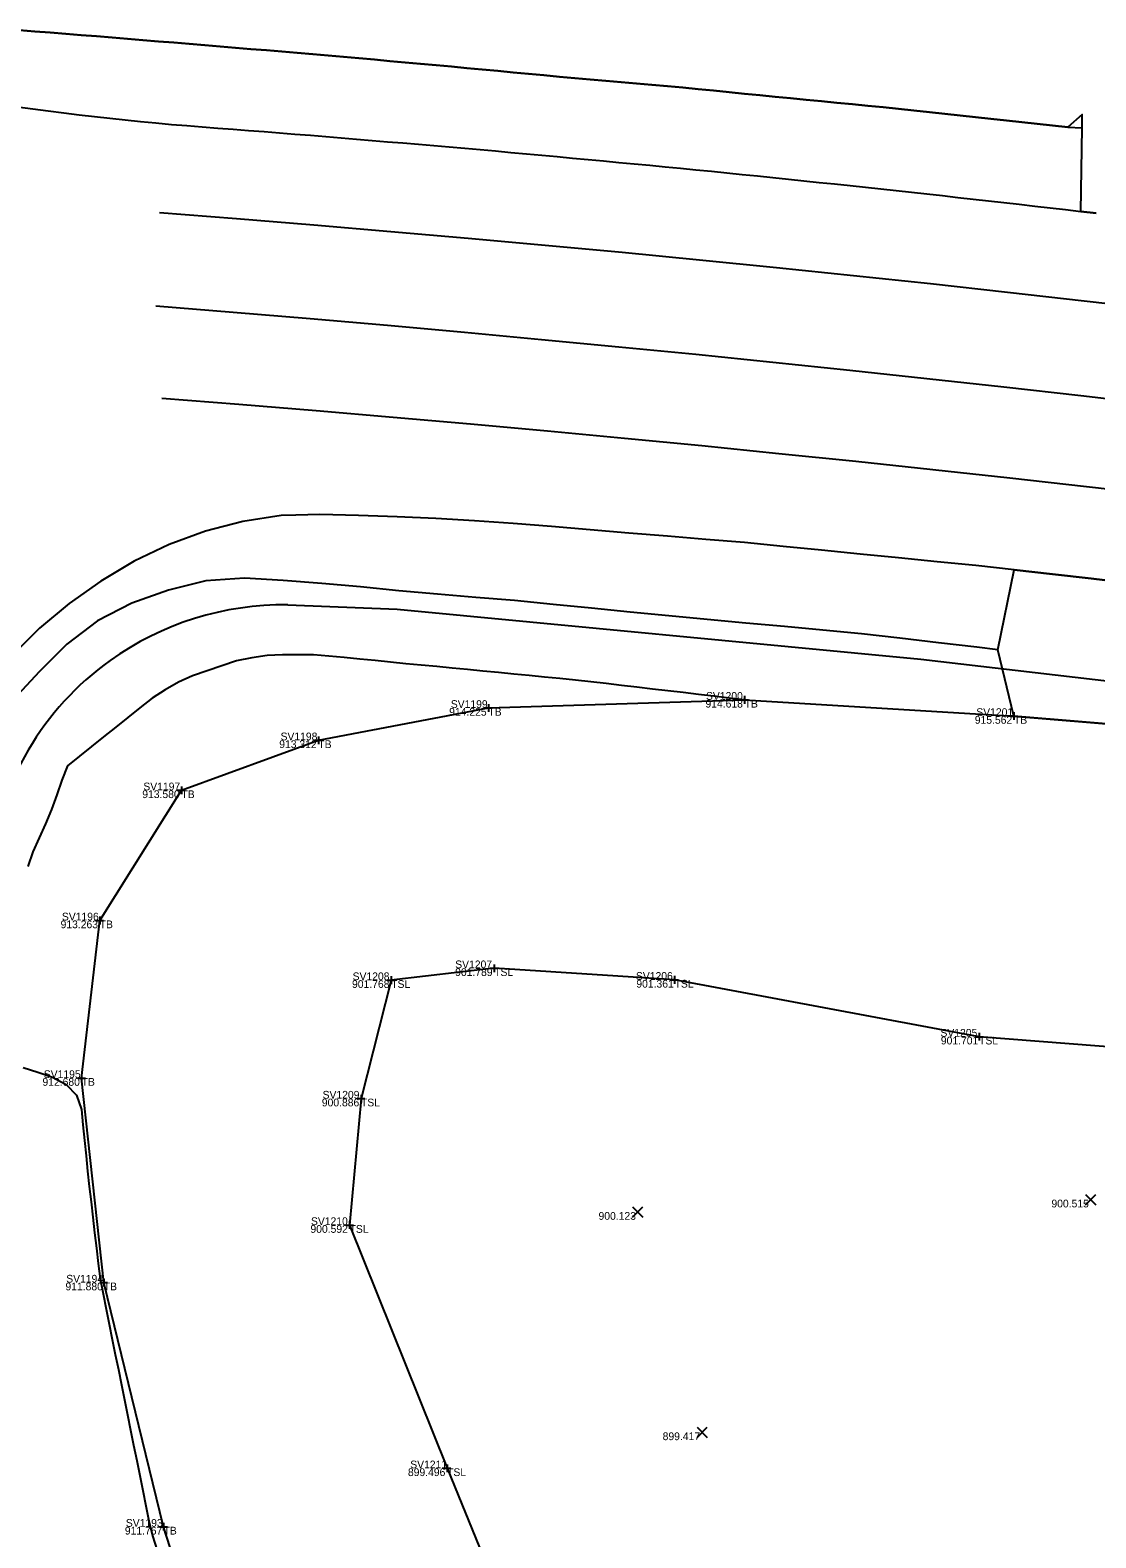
# Model space of a CAD drawing. Extents: x 1918148 to 1919797, y 624701 to 627089.
# Drawn here: x 1918938.4 to 1919076, y 625706.2 to 625900.9 of the extents above; entities that cross this region are included whole.
import ezdxf

# ---------------------------------------------------------------- set-up
doc = ezdxf.new("R2010")
doc.units = 0
for name, color, linetype in [('DT_X_Terrain_Boundary', 7, 'Continuous'), ('PM_X_Channelizing_Line', 7, 'Continuous'), ('PM_X_CL_Double_Solid', 7, 'Continuous'), ('PM_X_Edge_Line', 7, 'Continuous'), ('PM_X_Lane_Line', 7, 'Continuous'), ('PV_X_Shoulder_Aggregate', 7, 'Continuous'), ('RD_X_Concrete_Pad', 7, 'Continuous'), ('RD_X_GR_Rt', 7, 'Continuous'), ('SV_X_Random_Point', 7, 'Continuous'), ('SV_X_Shot_Marker', 7, 'Continuous'), ('SV_X_Text_Comment', 7, 'Continuous'), ('SV_X_Text_Elevation', 7, 'Continuous'), ('SV_X_Text_Name', 7, 'Continuous'), ('SV_X_Toe_of_Slope', 7, 'Continuous'), ('SV_X_Top_of_Bank', 7, 'Continuous')]:
    doc.layers.add(name, color=color, linetype=linetype)

msp = doc.modelspace()

# ---------------------------------------------------------------- linework, layer by layer
at = {"layer": 'DT_X_Terrain_Boundary'}
for points in [[(1919076.08, 625877.29), (1919074.09, 625877.53), (1919074.28, 625888.32), (1919074.28, 625890.06), (1919072.42, 625888.4), (1919070.43, 625888.62), (1919068.44, 625888.84), (1919066.45, 625889.05), (1919064.47, 625889.27), (1919062.48, 625889.49), (1919060.49, 625889.71), (1919058.5, 625889.92), (1919056.51, 625890.14), (1919054.53, 625890.36), (1919052.54, 625890.57), (1919050.55, 625890.77), (1919048.56, 625890.97), (1919046.57, 625891.16), (1919044.58, 625891.36), (1919042.59, 625891.55), (1919040.6, 625891.75), (1919038.6, 625891.95), (1919036.61, 625892.14), (1919034.62, 625892.34), (1919032.63, 625892.54), (1919030.64, 625892.73), (1919028.65, 625892.93), (1919026.66, 625893.12), (1919024.67, 625893.32), (1919022.68, 625893.52), (1919020.69, 625893.7), (1919018.7, 625893.88), (1919016.71, 625894.05), (1919014.71, 625894.23), (1919012.72, 625894.4), (1919010.73, 625894.56), (1919008.73, 625894.73), (1919006.74, 625894.91), (1919004.75, 625895.1), (1919002.76, 625895.29), (1919000.77, 625895.48), (1918998.78, 625895.66), (1918996.79, 625895.85), (1918994.8, 625896.04), (1918992.8, 625896.22), (1918990.81, 625896.4), (1918988.82, 625896.59), (1918986.83, 625896.77), (1918984.84, 625896.95), (1918982.85, 625897.13), (1918980.85, 625897.31), (1918978.86, 625897.49), (1918976.87, 625897.66), (1918974.88, 625897.83), (1918972.88, 625898), (1918970.89, 625898.17), (1918968.9, 625898.34), (1918966.9, 625898.5), (1918964.91, 625898.67), (1918962.92, 625898.83), (1918960.93, 625899), (1918958.93, 625899.16), (1918956.94, 625899.33), (1918954.95, 625899.49), (1918952.95, 625899.65), (1918950.96, 625899.82), (1918948.97, 625899.98), (1918946.97, 625900.14), (1918944.98, 625900.3), (1918942.98, 625900.46), (1918940.99, 625900.62), (1918939, 625900.78), (1918937, 625900.93)], [(1919200.65, 625791.17), (1919111.29, 625808.54), (1919090.36, 625810.28), (1919065.45, 625812.35), (1919063.39, 625820.89), (1919065.48, 625831.23), (1919070.44, 625830.66), (1919075.41, 625830.09), (1919080.38, 625829.52), (1919085.35, 625828.96), (1919090.31, 625828.39), (1919095.28, 625827.8), (1919100.24, 625827.2), (1919105.21, 625826.6), (1919110.17, 625826), (1919115.14, 625825.41), (1919120.1, 625824.81), (1919124.48, 625836), (1919134.4, 625834.72), (1919144.31, 625833.4), (1919154.22, 625832.06)]]:
    msp.add_lwpolyline(points, dxfattribs=at)
at = {"layer": 'PM_X_Channelizing_Line'}
msp.add_lwpolyline([(1918955.09, 625877.37), (1918965.06, 625876.6), (1918975.03, 625875.79), (1918984.99, 625874.95), (1918994.95, 625874.08), (1919004.91, 625873.18), (1919014.87, 625872.24), (1919024.82, 625871.28), (1919034.77, 625870.28), (1919044.72, 625869.26), (1919054.67, 625868.2), (1919064.61, 625867.11), (1919074.54, 625865.99), (1919084.48, 625864.84), (1919094.41, 625863.66), (1919104.33, 625862.45), (1919114.25, 625861.2), (1919124.17, 625859.93), (1919134.09, 625858.62), (1919144, 625857.29), (1919153.9, 625855.92), (1919160.39, 625855.01)], dxfattribs=at)
at = {"layer": 'PM_X_CL_Double_Solid'}
msp.add_lwpolyline([(1918954.64, 625865.34), (1918964.6, 625864.53), (1918974.57, 625863.69), (1918984.53, 625862.82), (1918994.49, 625861.93), (1919004.45, 625861), (1919014.4, 625860.05), (1919024.35, 625859.07), (1919034.3, 625858.06), (1919044.25, 625857.03), (1919054.19, 625855.96), (1919064.13, 625854.87), (1919074.07, 625853.75), (1919084, 625852.6), (1919093.93, 625851.42), (1919103.86, 625850.22), (1919113.79, 625848.98), (1919123.71, 625847.72), (1919133.62, 625846.43), (1919143.53, 625845.11), (1919153.44, 625843.77), (1919160.7, 625842.77)], dxfattribs=at)
at = {"layer": 'PM_X_Edge_Line'}
for points in [[(1918936.77, 625891.05), (1918938.75, 625890.76), (1918940.73, 625890.5), (1918942.72, 625890.25), (1918944.7, 625890.01), (1918946.69, 625889.77), (1918948.67, 625889.55), (1918950.66, 625889.34), (1918952.65, 625889.14), (1918954.64, 625888.95), (1918956.64, 625888.77), (1918958.63, 625888.6), (1918960.62, 625888.44), (1918962.62, 625888.29), (1918964.61, 625888.14), (1918966.61, 625887.98), (1918968.6, 625887.83), (1918970.59, 625887.67), (1918972.59, 625887.51), (1918974.58, 625887.35), (1918976.57, 625887.19), (1918978.57, 625887.03), (1918980.56, 625886.87), (1918982.55, 625886.7), (1918984.55, 625886.53), (1918986.54, 625886.37), (1918988.53, 625886.2), (1918990.53, 625886.03), (1918992.52, 625885.85), (1918994.51, 625885.68), (1918996.5, 625885.5), (1918998.49, 625885.33), (1919000.49, 625885.15), (1919002.48, 625884.97), (1919004.47, 625884.79), (1919006.46, 625884.6), (1919008.45, 625884.42), (1919010.44, 625884.23), (1919012.44, 625884.05), (1919014.43, 625883.86), (1919016.42, 625883.67), (1919018.41, 625883.48), (1919020.4, 625883.28), (1919022.39, 625883.09), (1919024.38, 625882.89), (1919026.37, 625882.7), (1919028.36, 625882.5), (1919030.35, 625882.3), (1919032.34, 625882.1), (1919034.33, 625881.89), (1919036.32, 625881.69), (1919038.31, 625881.48), (1919040.3, 625881.27), (1919042.29, 625881.07), (1919044.28, 625880.86), (1919046.26, 625880.64), (1919048.25, 625880.43), (1919050.24, 625880.22), (1919052.23, 625880), (1919054.22, 625879.78), (1919056.21, 625879.56), (1919058.19, 625879.34), (1919060.18, 625879.12), (1919062.17, 625878.9), (1919064.16, 625878.67), (1919066.14, 625878.45), (1919068.13, 625878.22), (1919070.12, 625877.99), (1919072.1, 625877.76), (1919074.09, 625877.53), (1919076.08, 625877.29)], [(1918972.72, 625838.3), (1918970.79, 625838.25), (1918965.86, 625837.46), (1918961.02, 625836.21), (1918956.33, 625834.49), (1918951.81, 625832.35), (1918947.52, 625829.78), (1918943.44, 625826.9), (1918939.6, 625823.69), (1918936.06, 625820.17)], [(1919080.38, 625829.52), (1919075.41, 625830.09), (1919070.44, 625830.66), (1919065.48, 625831.23), (1919060.51, 625831.78), (1919055.53, 625832.27), (1919050.56, 625832.77), (1919045.58, 625833.27), (1919040.61, 625833.76), (1919035.63, 625834.26), (1919030.65, 625834.74), (1919025.67, 625835.15), (1919020.69, 625835.57), (1919015.7, 625835.98), (1919010.72, 625836.4), (1919005.74, 625836.81), (1919000.76, 625837.22), (1918995.77, 625837.56), (1918990.78, 625837.85), (1918985.78, 625838.08), (1918980.78, 625838.26), (1918975.79, 625838.38), (1918972.72, 625838.3)]]:
    msp.add_lwpolyline(points, dxfattribs=at)
at = {"layer": 'PM_X_Lane_Line'}
msp.add_lwpolyline([(1918955.39, 625853.42), (1918965.36, 625852.63), (1918975.33, 625851.81), (1918985.29, 625850.96), (1918995.25, 625850.08), (1919005.21, 625849.17), (1919015.17, 625848.23), (1919025.12, 625847.27), (1919035.07, 625846.27), (1919045.02, 625845.25), (1919054.96, 625844.19), (1919064.9, 625843.11), (1919074.84, 625842), (1919084.78, 625840.86), (1919094.71, 625839.69), (1919104.63, 625838.49), (1919114.56, 625837.26), (1919124.48, 625836), (1919134.4, 625834.72), (1919144.31, 625833.4), (1919154.22, 625832.06), (1919164.12, 625830.68), (1919174.03, 625829.28), (1919193.35, 625826.46)], dxfattribs=at)
at = {"layer": 'PV_X_Shoulder_Aggregate'}
for points in [[(1919030.67, 625814.44), (1919028.68, 625814.67), (1919026.69, 625814.91), (1919024.71, 625815.14), (1919022.72, 625815.37), (1919020.73, 625815.6), (1919018.75, 625815.83), (1919016.76, 625816.06), (1919014.77, 625816.3), (1919012.79, 625816.53), (1919010.8, 625816.76), (1919008.82, 625816.99), (1919006.82, 625817.19), (1919004.83, 625817.38), (1919002.84, 625817.57), (1919000.85, 625817.76), (1918998.86, 625817.96), (1918996.87, 625818.15), (1918994.88, 625818.34), (1918992.89, 625818.54), (1918990.9, 625818.73), (1918988.91, 625818.92), (1918986.92, 625819.11), (1918984.93, 625819.31), (1918982.94, 625819.5), (1918980.95, 625819.69), (1918978.96, 625819.89), (1918976.96, 625820.08), (1918974.97, 625820.24), (1918972.98, 625820.26), (1918970.98, 625820.27), (1918968.98, 625820.16), (1918967, 625819.86), (1918965.05, 625819.49), (1918963.16, 625818.83), (1918961.27, 625818.18), (1918959.37, 625817.53), (1918957.56, 625816.71), (1918955.81, 625815.75), (1918954.13, 625814.67), (1918952.57, 625813.42), (1918951.01, 625812.17), (1918949.45, 625810.92), (1918947.88, 625809.67), (1918946.32, 625808.42), (1918944.76, 625807.17), (1918943.2, 625805.92), (1918942.5, 625804.05), (1918941.83, 625802.17), (1918941.16, 625800.28), (1918940.38, 625798.44), (1918939.56, 625796.62), (1918938.74, 625794.79), (1918938.08, 625792.91)], [(1918937.48, 625766.95), (1918939.38, 625766.34), (1918941.26, 625765.69), (1918943.03, 625764.75), (1918944.38, 625763.36), (1918945.02, 625761.52), (1918945.21, 625759.53), (1918945.41, 625757.54), (1918945.61, 625755.55), (1918945.81, 625753.56), (1918946.01, 625751.57), (1918946.25, 625749.59), (1918946.48, 625747.6), (1918946.71, 625745.61), (1918946.95, 625743.63), (1918947.18, 625741.64), (1918947.42, 625739.66), (1918947.82, 625737.7), (1918948.21, 625735.75), (1918948.6, 625733.8), (1918949, 625731.84), (1918949.39, 625729.89), (1918949.79, 625727.94), (1918950.18, 625725.98), (1918950.57, 625724.03), (1918950.97, 625722.08), (1918951.36, 625720.12), (1918951.75, 625718.17), (1918952.15, 625716.21), (1918952.54, 625714.26), (1918952.93, 625712.31), (1918953.33, 625710.35), (1918953.72, 625708.4), (1918954.19, 625706.47), (1918954.81, 625704.56)]]:
    msp.add_lwpolyline(points, dxfattribs=at)
at = {"layer": 'RD_X_Concrete_Pad'}
for points in [[(1918937, 625900.93), (1918939, 625900.78), (1918940.99, 625900.62), (1918942.98, 625900.46), (1918944.98, 625900.3), (1918946.97, 625900.14), (1918948.97, 625899.98), (1918950.96, 625899.82), (1918952.95, 625899.65), (1918954.95, 625899.49), (1918956.94, 625899.33), (1918958.93, 625899.16), (1918960.93, 625899), (1918962.92, 625898.83), (1918964.91, 625898.67), (1918966.9, 625898.5), (1918968.9, 625898.34), (1918970.89, 625898.17), (1918972.88, 625898), (1918974.88, 625897.83), (1918976.87, 625897.66), (1918978.86, 625897.49), (1918980.85, 625897.31), (1918982.85, 625897.13), (1918984.84, 625896.95), (1918986.83, 625896.77), (1918988.82, 625896.59), (1918990.81, 625896.4), (1918992.8, 625896.22), (1918994.8, 625896.04), (1918996.79, 625895.85), (1918998.78, 625895.66), (1919000.77, 625895.48), (1919002.76, 625895.29), (1919004.75, 625895.1), (1919006.74, 625894.91), (1919008.73, 625894.73), (1919010.73, 625894.56), (1919012.72, 625894.4), (1919014.71, 625894.23), (1919016.71, 625894.05), (1919018.7, 625893.88), (1919020.69, 625893.7), (1919022.68, 625893.52), (1919024.67, 625893.32), (1919026.66, 625893.12), (1919028.65, 625892.93), (1919030.64, 625892.73), (1919032.63, 625892.54), (1919034.62, 625892.34), (1919036.61, 625892.14), (1919038.6, 625891.95), (1919040.6, 625891.75), (1919042.59, 625891.55), (1919044.58, 625891.36), (1919046.57, 625891.16), (1919048.56, 625890.97), (1919050.55, 625890.77), (1919052.54, 625890.57), (1919054.53, 625890.36), (1919056.51, 625890.14), (1919058.5, 625889.92), (1919060.49, 625889.71), (1919062.48, 625889.49), (1919064.47, 625889.27), (1919066.45, 625889.05), (1919068.44, 625888.84), (1919070.43, 625888.62), (1919072.42, 625888.4), (1919074.28, 625888.32), (1919074.28, 625890.06)], [(1919063.39, 625820.89), (1919060.65, 625821.25), (1919055.69, 625821.82), (1919050.72, 625822.39), (1919045.75, 625822.95), (1919040.77, 625823.42), (1919035.8, 625823.89), (1919030.82, 625824.36), (1919025.84, 625824.83), (1919020.86, 625825.3), (1919015.88, 625825.77), (1919010.91, 625826.27), (1919005.93, 625826.76), (1919000.96, 625827.25), (1918995.97, 625827.67), (1918990.99, 625828.09), (1918986.01, 625828.53), (1918981.04, 625829.03), (1918976.06, 625829.47), (1918971.07, 625829.85), (1918966.08, 625830.16), (1918961.1, 625829.79), (1918956.25, 625828.6), (1918951.54, 625826.92), (1918947.09, 625824.66), (1918943.11, 625821.64), (1918939.58, 625818.11), (1918936.21, 625814.42)]]:
    msp.add_lwpolyline(points, dxfattribs=at)
at = {"layer": 'RD_X_GR_Rt'}
msp.add_lwpolyline([(1918971.66, 625826.7), (1918985.81, 625826.14), (1919053.44, 625819.71), (1919110.63, 625813)], dxfattribs=at)
for centre, radius, start, end in [((1918971.1, 625788.29), 38.41, 89.1608, 125.641), ((1918970.05, 625789.38), 36.91, 125.2973, 174.3384)]:
    msp.add_arc(centre, radius, start, end, dxfattribs=at)
at = {"layer": 'SV_X_Random_Point'}
for p, q in [((1919074.69, 625749.22), (1919076.02, 625750.55)), ((1919074.69, 625750.55), (1919076.02, 625749.22)), ((1919016.18, 625747.62), (1919017.51, 625748.95)), ((1919016.18, 625748.95), (1919017.51, 625747.62)), ((1919024.52, 625719.15), (1919025.85, 625720.49)), ((1919024.52, 625720.49), (1919025.85, 625719.15))]:
    msp.add_line(p, q, dxfattribs=at)
at = {"layer": 'SV_X_Shot_Marker'}
for p, q in [((1919030.17, 625814.44), (1919031.17, 625814.44)), ((1919030.67, 625814.94), (1919030.67, 625813.94)), ((1919030.67, 625814.44), (1919030.67, 625814.44)), ((1918997.08, 625813.39), (1918998.08, 625813.39)), ((1918997.58, 625813.89), (1918997.58, 625812.89)), ((1918997.58, 625813.39), (1918997.58, 625813.39)), ((1919064.95, 625812.35), (1919065.95, 625812.35)), ((1919065.45, 625812.85), (1919065.45, 625811.85)), ((1919065.45, 625812.35), (1919065.45, 625812.35)), ((1918975.11, 625809.21), (1918976.11, 625809.21)), ((1918975.61, 625809.71), (1918975.61, 625808.71)), ((1918975.61, 625809.21), (1918975.61, 625809.21)), ((1918957.43, 625802.75), (1918958.43, 625802.75)), ((1918957.93, 625803.25), (1918957.93, 625802.25)), ((1918957.93, 625802.75), (1918957.93, 625802.75)), ((1918946.87, 625785.94), (1918947.87, 625785.94)), ((1918947.37, 625786.44), (1918947.37, 625785.44)), ((1918947.37, 625785.94), (1918947.37, 625785.94)), ((1918997.82, 625779.77), (1918998.82, 625779.77)), ((1918998.32, 625780.27), (1918998.32, 625779.27)), ((1918998.32, 625779.77), (1918998.32, 625779.77)), ((1918984.52, 625778.23), (1918985.52, 625778.23)), ((1918985.02, 625778.73), (1918985.02, 625777.73)), ((1918985.02, 625778.23), (1918985.02, 625778.23)), ((1919021.12, 625778.27), (1919022.12, 625778.27)), ((1919021.62, 625778.77), (1919021.62, 625777.77)), ((1919021.62, 625778.27), (1919021.62, 625778.27)), ((1919060.95, 625771.43), (1919060.95, 625770.43)), ((1919060.45, 625770.93), (1919061.45, 625770.93)), ((1919060.95, 625770.93), (1919060.95, 625770.93)), ((1918944.54, 625765.59), (1918945.54, 625765.59)), ((1918945.04, 625766.09), (1918945.04, 625765.09)), ((1918945.04, 625765.59), (1918945.04, 625765.59)), ((1918981.12, 625763.43), (1918981.12, 625762.43)), ((1918980.62, 625762.93), (1918981.62, 625762.93)), ((1918981.12, 625762.93), (1918981.12, 625762.93)), ((1918979.14, 625746.6), (1918980.14, 625746.6)), ((1918979.64, 625747.1), (1918979.64, 625746.1)), ((1918979.64, 625746.6), (1918979.64, 625746.6)), ((1918947.4, 625739.17), (1918948.4, 625739.17)), ((1918947.9, 625739.67), (1918947.9, 625738.67)), ((1918947.9, 625739.17), (1918947.9, 625739.17)), ((1918991.74, 625715.18), (1918992.74, 625715.18)), ((1918992.24, 625715.68), (1918992.24, 625714.68)), ((1918992.24, 625715.18), (1918992.24, 625715.18)), ((1918955.12, 625707.63), (1918956.12, 625707.63)), ((1918955.62, 625708.13), (1918955.62, 625707.13)), ((1918955.62, 625707.63), (1918955.62, 625707.63))]:
    msp.add_line(p, q, dxfattribs=at)
at = {"layer": 'SV_X_Toe_of_Slope'}
msp.add_lwpolyline([(1919144.35, 625769.58), (1919100.27, 625767.87), (1919060.95, 625770.93), (1919021.62, 625778.27), (1918998.32, 625779.77), (1918985.02, 625778.23), (1918981.12, 625762.93), (1918979.64, 625746.6), (1918992.24, 625715.18), (1919001.08, 625693.54), (1919008.19, 625681.54), (1919013.95, 625671.92), (1919018.79, 625665.98), (1919022.16, 625659.12), (1919025.26, 625652.5), (1919028.92, 625643.15)], dxfattribs=at)
at = {"layer": 'SV_X_Top_of_Bank'}
msp.add_lwpolyline([(1919180.03, 625377.77), (1919142.39, 625420.85), (1919113.9, 625458.17), (1919086.6, 625489.42), (1919057.39, 625523.08), (1919019.76, 625570.22), (1918998.07, 625602.27), (1918985.26, 625627.56), (1918968.39, 625668.03), (1918955.62, 625707.63), (1918947.9, 625739.17), (1918945.04, 625765.59), (1918947.37, 625785.94), (1918957.93, 625802.75), (1918975.61, 625809.21), (1918997.58, 625813.39), (1919030.67, 625814.44), (1919065.45, 625812.35), (1919111.29, 625808.54)], dxfattribs=at)

# ---------------------------------------------------------------- texts
at = {"layer": 'SV_X_Text_Comment'}
for s, p in [('TB', (1919030.67, 625813.44)), ('TB', (1918997.58, 625812.39)), ('TB', (1919065.45, 625811.35)), ('TB', (1918975.61, 625808.21)), ('TB', (1918957.93, 625801.75)), ('TB', (1918947.37, 625784.94)), ('TSL', (1918998.32, 625778.77)), ('TSL', (1918985.02, 625777.23)), ('TSL', (1919021.62, 625777.27)), ('TSL', (1919060.95, 625769.93)), ('TB', (1918945.04, 625764.59)), ('TSL', (1918981.12, 625761.93)), ('TSL', (1918979.64, 625745.6)), ('TB', (1918947.9, 625738.17)), ('TSL', (1918992.24, 625714.18)), ('TB', (1918955.62, 625706.63))]:
    msp.add_text(s, height=1, dxfattribs=at).set_placement(p)
at = {"layer": 'SV_X_Text_Elevation'}
for s, p in [('914.618', (1919025.61, 625813.44)), ('914.225', (1918992.51, 625812.39)), ('915.562', (1919060.39, 625811.35)), ('913.312', (1918970.56, 625808.21)), ('913.580', (1918952.87, 625801.75)), ('913.263', (1918942.32, 625784.94)), ('901.789', (1918993.28, 625778.77)), ('901.768', (1918979.96, 625777.23)), ('901.361', (1919016.68, 625777.27)), ('901.701', (1919056.01, 625769.93)), ('912.680', (1918939.98, 625764.59)), ('900.886', (1918976.06, 625761.93)), ('900.515', (1919070.29, 625748.88)), ('900.123', (1919011.8, 625747.28)), ('900.592', (1918974.59, 625745.6)), ('911.880', (1918942.95, 625738.17)), ('899.417', (1919020.08, 625718.82)), ('899.496', (1918987.18, 625714.18)), ('911.767', (1918950.62, 625706.63))]:
    msp.add_text(s, height=1, dxfattribs=at).set_placement(p)
at = {"layer": 'SV_X_Text_Name'}
for s, p in [('SV1199', (1918992.72, 625813.39)), ('SV1200', (1919025.68, 625814.44)), ('SV1201', (1919060.59, 625812.35)), ('SV1198', (1918970.73, 625809.21)), ('SV1197', (1918953.01, 625802.75)), ('SV1196', (1918942.49, 625785.94)), ('SV1208', (1918980.04, 625778.23)), ('SV1207', (1918993.29, 625779.77)), ('SV1206', (1919016.63, 625778.27)), ('SV1205', (1919055.96, 625770.93)), ('SV1195', (1918940.15, 625765.59)), ('SV1209', (1918976.16, 625762.93)), ('SV1210', (1918974.66, 625746.6)), ('SV1194', (1918943.05, 625739.17)), ('SV1211', (1918987.48, 625715.18)), ('SV1193', (1918950.75, 625707.63))]:
    msp.add_text(s, height=1, dxfattribs=at).set_placement(p)

doc.saveas('drawing.dxf')
